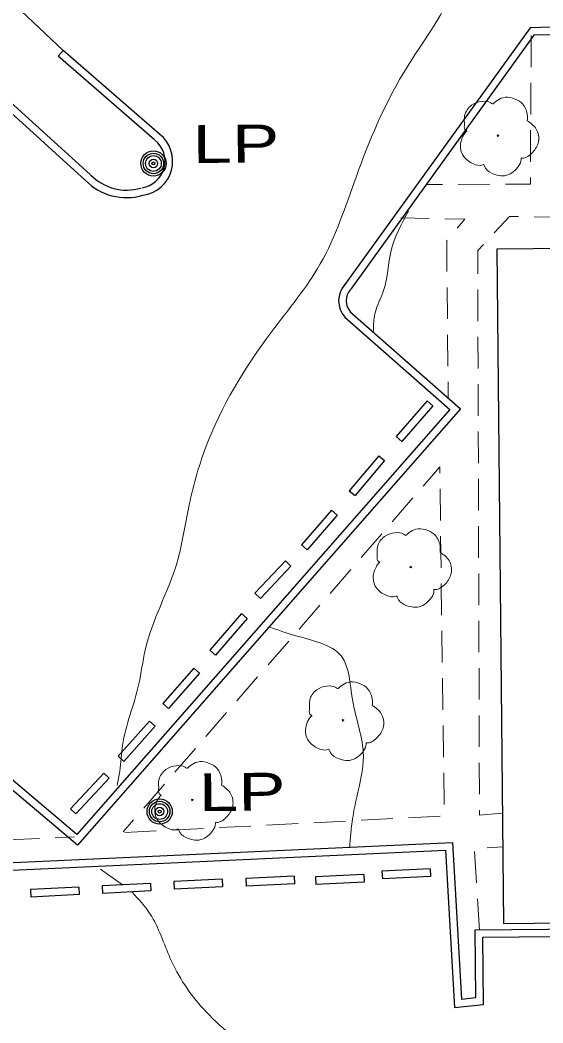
# Model space of a CAD drawing. Extents: x 2361708 to 2370558, y 6977955 to 6991887.
# Drawn here: x 2368967.1 to 2369033.4, y 6989957 to 6990084.2 of the extents above; entities that cross this region are included whole.
import ezdxf

# ---------------------------------------------------------------- set-up
doc = ezdxf.new("R2010")
doc.units = 0
doc.header["$LTSCALE"] = 1.9
for name, color, linetype, lineweight in [('11', 7, 'Continuous', 25), ('13', 7, 'Continuous', 13), ('2', 7, 'Continuous', 25), ('20', 7, 'Continuous', 25), ('29', 7, 'Continuous', 13), ('35', 7, 'Continuous', 13)]:
    doc.layers.add(name, color=color, linetype=linetype, lineweight=lineweight)

msp = doc.modelspace()

# ---------------------------------------------------------------- linework, layer by layer
at = {"layer": '11'}
msp.add_lwpolyline([(2369027.535, 6990055.151), (2369028.399, 6989969.665), (2369096.246, 6989970.351), (2369096.066, 6989988.181), (2369102.336, 6989988.24), (2369102.413, 6989980.191), (2369110.452, 6989980.267), (2369110.378, 6989988.067), (2369111.958, 6989988.082), (2369111.312, 6990055.949)], close=True, dxfattribs=at)
at = {"layer": '13'}
for p, q in [((2369031.896, 6990078.264), (2369031.917, 6990082.264)), ((2369031.853, 6990072.263), (2369031.885, 6990076.264)), ((2369031.82, 6990066.263), (2369031.842, 6990070.263)), ((2369018.657, 6990063.357), (2369020.657, 6990063.366)), ((2369022.657, 6990063.375), (2369026.657, 6990063.393)), ((2369018.957, 6990059.06), (2369015.387, 6990059.146)), ((2369036.286, 6990059.245), (2369032.286, 6990059.287)), ((2369021.289, 6990046.322), (2369021.251, 6990050.321)), ((2369025.144, 6990050.038), (2369025.152, 6990046.038)), ((2369021.346, 6990040.322), (2369021.308, 6990044.322)), ((2369025.161, 6990044.038), (2369025.169, 6990040.038)), ((2369021.384, 6990036.322), (2369021.365, 6990038.322)), ((2369025.178, 6990038.038), (2369025.196, 6990034.038)), ((2369025.205, 6990032.038), (2369025.213, 6990028.038)), ((2369025.222, 6990026.038), (2369025.23, 6990022.038)), ((2369020.354, 6990024.752), (2369020.402, 6990020.752)), ((2369014.283, 6990020.594), (2369016.905, 6990023.619)), ((2369025.239, 6990020.038), (2369025.247, 6990016.038)), ((2369010.347, 6990016.056), (2369012.968, 6990019.081)), ((2369020.432, 6990018.752), (2369020.479, 6990014.752)), ((2369006.41, 6990011.518), (2369009.031, 6990014.543)), ((2369025.256, 6990014.038), (2369025.274, 6990010.038)), ((2369020.509, 6990012.752), (2369020.557, 6990008.753)), ((2369002.473, 6990006.98), (2369005.094, 6990010.006)), ((2369025.284, 6990008.038), (2369025.292, 6990004.038)), ((2369020.586, 6990006.753), (2369020.634, 6990002.753)), ((2368998.536, 6990002.443), (2369001.157, 6990005.468)), ((2369025.301, 6990002.038), (2369025.309, 6989998.038)), ((2368994.599, 6989997.905), (2368997.22, 6990000.93)), ((2369020.663, 6990000.753), (2369020.711, 6989996.753)), ((2368990.662, 6989993.368), (2368993.283, 6989996.393)), ((2369025.318, 6989996.038), (2369025.326, 6989992.037)), ((2369020.74, 6989994.754), (2369020.788, 6989990.754)), ((2368986.725, 6989988.83), (2368989.346, 6989991.855)), ((2369025.335, 6989990.037), (2369025.353, 6989986.037)), ((2369020.817, 6989988.754), (2369020.865, 6989984.754)), ((2368982.788, 6989984.292), (2368985.409, 6989987.317)), ((2368980.167, 6989981.267), (2368981.472, 6989982.779)), ((2369008.355, 6989982.635), (2369004.356, 6989982.427)), ((2369014.351, 6989982.952), (2369010.354, 6989982.744)), ((2369020.349, 6989983.259), (2369016.351, 6989983.051)), ((2368984.365, 6989981.387), (2368980.367, 6989981.179)), ((2368990.362, 6989981.704), (2368986.365, 6989981.496)), ((2368996.36, 6989982.011), (2368992.362, 6989981.803)), ((2369002.357, 6989982.328), (2368998.359, 6989982.12)), ((2368965.555, 6989980.248), (2368969.553, 6989980.436)), ((2368971.553, 6989980.525), (2368974.012, 6989980.638)), ((2369024.722, 6989978.771), (2369024.98, 6989974.783)), ((2369028.337, 6989979.356), (2369026.338, 6989979.236)), ((2369025.109, 6989972.784), (2369025.367, 6989968.796))]:
    msp.add_line(p, q, dxfattribs=at)
for points in [[(2369028.657, 6990063.403), (2369031.807, 6990063.412), (2369031.809, 6990064.262)], [(2369022.539, 6990057.834), (2369023.489, 6990058.953), (2369020.958, 6990059.009)], [(2369030.286, 6990059.308), (2369029.156, 6990059.327), (2369027.205, 6990057.218)], [(2369021.232, 6990052.321), (2369021.205, 6990056.261), (2369021.244, 6990056.311)], [(2369025.85, 6990055.755), (2369025.127, 6990054.978), (2369025.135, 6990052.038)], [(2369018.221, 6990025.131), (2369020.317, 6990027.551), (2369020.325, 6990026.751)], [(2369025.352, 6989984.037), (2369025.358, 6989983.377), (2369028.196, 6989983.624)]]:
    msp.add_lwpolyline(points, dxfattribs=at)
at = {"layer": '2'}
for p, q in [((2368967.234, 6990085.399), (2368972.543, 6990080.379)), ((2368971.909, 6990079.653), (2368972.563, 6990080.36)), ((2368984.151, 6990069.029), (2368971.909, 6990079.653)), ((2368984.784, 6990069.755), (2368972.543, 6990080.379)), ((2369018.718, 6990035.927), (2369014.781, 6990031.399)), ((2369019.444, 6990035.293), (2369015.507, 6990030.766)), ((2369018.718, 6990035.927), (2369019.444, 6990035.293)), ((2369014.781, 6990031.399), (2369015.507, 6990030.766)), ((2369012.594, 6990028.978), (2369008.836, 6990024.532)), ((2369013.33, 6990028.355), (2369009.572, 6990023.909)), ((2369012.594, 6990028.978), (2369013.33, 6990028.355)), ((2369008.836, 6990024.532), (2369009.572, 6990023.909)), ((2369006.599, 6990022.06), (2369002.791, 6990017.664)), ((2369006.599, 6990022.06), (2369007.325, 6990021.427)), ((2369007.325, 6990021.427), (2369003.517, 6990017.031)), ((2369002.791, 6990017.664), (2369003.517, 6990017.031)), ((2369000.74, 6990015.624), (2368996.869, 6990011.547)), ((2369000.74, 6990015.624), (2369001.436, 6990014.961)), ((2369001.436, 6990014.961), (2368997.565, 6990010.884)), ((2368996.869, 6990011.547), (2368997.565, 6990010.884)), ((2368995.164, 6990008.941), (2368991.147, 6990004.323)), ((2368995.89, 6990008.308), (2368991.874, 6990003.69)), ((2368995.164, 6990008.941), (2368995.89, 6990008.308)), ((2368991.147, 6990004.323), (2368991.874, 6990003.69)), ((2368989.139, 6990002.043), (2368985.191, 6989997.565)), ((2368989.139, 6990002.043), (2368989.855, 6990001.41)), ((2368989.855, 6990001.41), (2368985.908, 6989996.933)), ((2368985.191, 6989997.565), (2368985.908, 6989996.933)), ((2368983.503, 6989995.3), (2368979.535, 6989990.852)), ((2368983.503, 6989995.3), (2368984.219, 6989994.656)), ((2368984.219, 6989994.656), (2368980.251, 6989990.208)), ((2368979.535, 6989990.852), (2368980.251, 6989990.208)), ((2368977.705, 6989988.714), (2368973.478, 6989984.203)), ((2368978.401, 6989988.061), (2368974.174, 6989983.55)), ((2368977.705, 6989988.714), (2368978.401, 6989988.061)), ((2368973.478, 6989984.203), (2368974.174, 6989983.55)), ((2369019.103, 6989976.577), (2369012.985, 6989976.269)), ((2369012.985, 6989976.269), (2369013.035, 6989975.31)), ((2369019.103, 6989976.577), (2369019.152, 6989975.618)), ((2368992.704, 6989975.276), (2368986.586, 6989974.968)), ((2368986.586, 6989974.968), (2368986.636, 6989974.008)), ((2368992.704, 6989975.276), (2368992.753, 6989974.316)), ((2369001.841, 6989975.653), (2368995.723, 6989975.345)), ((2368995.723, 6989975.345), (2368995.772, 6989974.385)), ((2369001.841, 6989975.653), (2369001.89, 6989974.693)), ((2369010.669, 6989975.857), (2369004.552, 6989975.549)), ((2369004.552, 6989975.549), (2369004.601, 6989974.589)), ((2369010.669, 6989975.857), (2369010.719, 6989974.898)), ((2369019.152, 6989975.618), (2369013.035, 6989975.31)), ((2368974.543, 6989974.263), (2368968.425, 6989973.955)), ((2368968.425, 6989973.955), (2368968.474, 6989972.995)), ((2368974.543, 6989974.263), (2368974.592, 6989973.304)), ((2368983.618, 6989974.739), (2368977.501, 6989974.431)), ((2368977.501, 6989974.431), (2368977.55, 6989973.472)), ((2368983.668, 6989973.78), (2368977.55, 6989973.472)), ((2368983.618, 6989974.739), (2368983.668, 6989973.78)), ((2368992.753, 6989974.316), (2368986.636, 6989974.008)), ((2369001.89, 6989974.693), (2368995.772, 6989974.385)), ((2369010.719, 6989974.898), (2369004.601, 6989974.589)), ((2368974.592, 6989973.304), (2368968.474, 6989972.995))]:
    msp.add_line(p, q, dxfattribs=at)
for points in [[(2369053.94, 6990080.024), (2369053.808, 6990063.432), (2369035.738, 6990063.35), (2369035.667, 6990083.35), (2369031.768, 6990083.233), (2369008.257, 6990050.678)], [(2369054.9, 6990080.013), (2369054.757, 6990062.481), (2369034.777, 6990062.381), (2369034.706, 6990082.361), (2369032.267, 6990082.288), (2369009.032, 6990050.115)], [(2368925.504, 6989999.047), (2368909.615, 6990014.627), (2368965.895, 6990073.816), (2368975.992, 6990064.631)], [(2368926.178, 6989999.734), (2368910.965, 6990014.65), (2368965.947, 6990072.476), (2368975.349, 6990063.925)], [(2369008.919, 6990047.274), (2369022.968, 6990034.927), (2368974.392, 6989979.602), (2368960.097, 6989991.646)], [(2369008.286, 6990046.558), (2369021.608, 6990034.844), (2368974.289, 6989980.941), (2368960.719, 6989992.382)], [(2368949.187, 6989978.892), (2368949.528, 6989975.665), (2369021.04, 6989978.936), (2369022.181, 6989958.976), (2369025.877, 6989959.381), (2369025.786, 6989967.9), (2369094.913, 6989968.528), (2369095.018, 6989970.139)], [(2368950.147, 6989978.991), (2368950.389, 6989976.663), (2369021.941, 6989979.935), (2369023.08, 6989960.045), (2369024.909, 6989960.242), (2369024.817, 6989968.851), (2369094.014, 6989969.48), (2369094.058, 6989970.12)]]:
    msp.add_lwpolyline(points, dxfattribs=at)
for centre, radius, start, end in [((2368982.069, 6990066.333), 4.369, 277.8722, 51.57746), ((2368982.069, 6990066.333), 3.409, 277.8722, 51.57746), ((2368980.586, 6990068.976), 6.316, 223.96883, 286.62951), ((2368980.586, 6990068.976), 7.276, 223.96883, 286.62951), ((2369010.611, 6990048.634), 3.117, 139.03888, 221.77675), ((2369010.611, 6990048.634), 2.157, 139.03888, 221.77675)]:
    msp.add_arc(centre, radius, start, end, dxfattribs=at)
at = {"layer": '20'}
for centre, radius in [((2368984, 6990066.038), 1.6), ((2368984, 6990066.038), 1.3), ((2368984, 6990066.038), 1), ((2368984, 6990066.038), 0.539), ((2368984, 6990066.038), 0.192), ((2368984.792, 6989983.841), 1.6), ((2368984.792, 6989983.841), 1.3), ((2368984.792, 6989983.841), 1), ((2368984.792, 6989983.841), 0.539), ((2368984.792, 6989983.841), 0.192)]:
    msp.add_circle(centre, radius, dxfattribs=at)
at = {"layer": '29'}
for centre in [(2369027.698, 6990069.574), (2369016.638, 6990014.856), (2369008.043, 6989995.423), (2368988.928, 6989985.321)]:
    msp.add_circle(centre, 0.1, dxfattribs=at)
for points in [[(2369023.732, 6990070.146), (2369023.752, 6990070.156), (2369023.672, 6990070.225), (2369023.435, 6990070.853), (2369023.474, 6990072.134), (2369024.361, 6990073.432), (2369025.666, 6990073.915), (2369026.788, 6990073.725), (2369027.019, 6990073.597), (2369027.089, 6990073.598), (2369027.139, 6990073.638), (2369027.487, 6990073.932), (2369028.352, 6990074.38), (2369029.563, 6990074.312), (2369030.679, 6990073.722), (2369031.412, 6990072.299), (2369031.421, 6990071.439)], [(2369031.41, 6990071.459), (2369032.55, 6990070.4), (2369032.835, 6990068.813), (2369032.128, 6990067.486), (2369031.473, 6990066.94), (2369030.805, 6990066.723), (2369030.656, 6990066.712), (2369030.637, 6990066.602), (2369030.315, 6990065.699), (2369028.776, 6990064.534), (2369026.883, 6990064.816), (2369025.984, 6990065.757), (2369025.913, 6990065.887), (2369025.793, 6990065.866), (2369024.582, 6990065.984), (2369023.313, 6990066.982), (2369022.967, 6990068.619), (2369023.337, 6990069.642), (2369023.663, 6990070.085), (2369023.732, 6990070.136)], [(2369012.673, 6990015.428), (2369012.693, 6990015.438), (2369012.612, 6990015.508), (2369012.376, 6990016.135), (2369012.414, 6990017.415), (2369013.301, 6990018.714), (2369014.607, 6990019.197), (2369015.729, 6990019.007), (2369015.96, 6990018.879), (2369016.03, 6990018.88), (2369016.08, 6990018.921), (2369016.427, 6990019.214), (2369017.293, 6990019.662), (2369018.503, 6990019.594), (2369019.619, 6990019.004), (2369020.352, 6990017.582), (2369020.361, 6990016.721)], [(2369020.351, 6990016.741), (2369021.491, 6990015.682), (2369021.776, 6990014.094), (2369021.068, 6990012.768), (2369020.413, 6990012.222), (2369019.746, 6990012.005), (2369019.596, 6990011.994), (2369019.577, 6990011.883), (2369019.255, 6990010.98), (2369017.716, 6990009.816), (2369015.824, 6990010.098), (2369014.925, 6990011.039), (2369014.853, 6990011.168), (2369014.733, 6990011.147), (2369013.522, 6990011.266), (2369012.253, 6990012.264), (2369011.907, 6990013.9), (2369012.277, 6990014.924), (2369012.603, 6990015.368), (2369012.673, 6990015.418)], [(2369004.077, 6989995.996), (2369004.097, 6989996.005), (2369004.016, 6989996.075), (2369003.78, 6989996.703), (2369003.818, 6989997.983), (2369004.706, 6989999.281), (2369006.011, 6989999.764), (2369007.133, 6989999.575), (2369007.365, 6989999.446), (2369007.435, 6989999.447), (2369007.484, 6989999.488), (2369007.831, 6989999.781), (2369008.697, 6990000.229), (2369009.908, 6990000.161), (2369011.023, 6989999.572), (2369011.757, 6989998.148), (2369011.765, 6989997.289)], [(2369011.755, 6989997.308), (2369012.895, 6989996.249), (2369013.18, 6989994.662), (2369012.473, 6989993.335), (2369011.818, 6989992.789), (2369011.15, 6989992.572), (2369011, 6989992.561), (2369010.981, 6989992.451), (2369010.66, 6989991.548), (2369009.121, 6989990.383), (2369007.228, 6989990.665), (2369006.329, 6989991.606), (2369006.258, 6989991.736), (2369006.138, 6989991.715), (2369004.927, 6989991.833), (2369003.657, 6989992.831), (2369003.312, 6989994.468), (2369003.682, 6989995.492), (2369004.008, 6989995.935), (2369004.077, 6989995.985)], [(2368984.962, 6989985.893), (2368984.982, 6989985.903), (2368984.902, 6989985.972), (2368984.666, 6989986.6), (2368984.703, 6989987.88), (2368985.591, 6989989.179), (2368986.897, 6989989.661), (2368988.019, 6989989.472), (2368988.25, 6989989.344), (2368988.32, 6989989.345), (2368988.369, 6989989.385), (2368988.717, 6989989.679), (2368989.583, 6989990.127), (2368990.793, 6989990.058), (2368991.909, 6989989.469), (2368992.642, 6989988.046), (2368992.65, 6989987.186)], [(2368992.64, 6989987.206), (2368993.781, 6989986.147), (2368994.066, 6989984.559), (2368993.358, 6989983.232), (2368992.703, 6989982.687), (2368992.035, 6989982.47), (2368991.885, 6989982.459), (2368991.866, 6989982.348), (2368991.545, 6989981.445), (2368990.006, 6989980.281), (2368988.113, 6989980.563), (2368987.214, 6989981.504), (2368987.143, 6989981.633), (2368987.023, 6989981.612), (2368985.812, 6989981.731), (2368984.543, 6989982.729), (2368984.197, 6989984.365), (2368984.567, 6989985.389), (2368984.893, 6989985.832), (2368984.962, 6989985.883)]]:
    msp.add_spline(points, degree=3, dxfattribs=at)
at = {"layer": '35'}
msp.add_line((2368977.301, 6989976.519), (2368980.09, 6989974.556), dxfattribs=at)
for points in [[(2369047.828, 6990605.451), (2369038.394, 6990593.231), (2369027.418, 6990575.906), (2369015.841, 6990558.825), (2369000.65, 6990535.639), (2368993.146, 6990516.056), (2368986.096, 6990501.379), (2368978.606, 6990487.716), (2368969.405, 6990472.988), (2368958.108, 6990456.92), (2368955.454, 6990452.025), (2368953.073, 6990437.411), (2368952.752, 6990420.737), (2368959.614, 6990409.992), (2368963.269, 6990401.087), (2368969.023, 6990386.05), (2368979.207, 6990379.327), (2368988.134, 6990377.652), (2368992.144, 6990375.52), (2368991.785, 6990372.277), (2368987.467, 6990362.585), (2368986.816, 6990353.218), (2368988.815, 6990341.807), (2368989.62, 6990331.804), (2368986.922, 6990311.667), (2368979.307, 6990292.194), (2368965.455, 6990270.221), (2368943.017, 6990245.776), (2368913.099, 6990212.86), (2368880.694, 6990176.38), (2368844.682, 6990139.715), (2368811.712, 6990113.21), (2368778.447, 6990087.292), (2368739.578, 6990051.33), (2368711.829, 6990035.275), (2368686.864, 6990022.057), (2368673.109, 6990014.046), (2368669.745, 6990012.454), (2368668.706, 6990013.324), (2368669.63, 6990016.033), (2368674.153, 6990022.016), (2368684.646, 6990033.407), (2368697.173, 6990050.577), (2368697.763, 6990054.743), (2368695.615, 6990054.522), (2368688.933, 6990050.498), (2368671.541, 6990036.962), (2368648.494, 6990028.152), (2368625.507, 6990018.213), (2368603.069, 6990007.409), (2368581.573, 6989999.594), (2368572.511, 6989995.447), (2368567.234, 6989993.027)], [(2368983.929, 6990531.529), (2368979.435, 6990519.356), (2368975.701, 6990506), (2368972.153, 6990495.326), (2368965.023, 6990482.667), (2368952.28, 6990464.985), (2368944.692, 6990449.112), (2368936.279, 6990436.661), (2368930.708, 6990428.388), (2368926.974, 6990420.332), (2368923.178, 6990407.345), (2368925.818, 6990397.9), (2368929.492, 6990388.004), (2368932.253, 6990381.66), (2368935.154, 6990377.288), (2368935.872, 6990367.074), (2368936.658, 6990350.711), (2368934.899, 6990336.894), (2368925.545, 6990315.203), (2368919.061, 6990298.721), (2368917.665, 6990291.017), (2368922.007, 6990291.848), (2368928.932, 6990298.725), (2368940.303, 6990308.073), (2368954.807, 6990321.422), (2368956.934, 6990318.642), (2368952.658, 6990309.771), (2368947.879, 6990300.145), (2368939.818, 6990283.488), (2368927.075, 6990259.465), (2368910.767, 6990240.319), (2368886.835, 6990212.09), (2368866.726, 6990187.627), (2368845.138, 6990163.161), (2368822.496, 6990139.104), (2368799.648, 6990117.845), (2368778.178, 6990104.05), (2368756.592, 6990085.654), (2368734.588, 6990065.974), (2368713.09, 6990048.828), (2368704.692, 6990045.508), (2368705.15, 6990046.662), (2368709.481, 6990052.884), (2368718.059, 6990061.596), (2368727.733, 6990071.708), (2368736.854, 6990082.166), (2368748.659, 6990097.399), (2368759.795, 6990109.476), (2368764.382, 6990117.239), (2368763.943, 6990120.186), (2368757.319, 6990118.552), (2368746.862, 6990109.793), (2368726.432, 6990091.817), (2368699.934, 6990071.484), (2368679.435, 6990058.628), (2368654.88, 6990046.464), (2368626.237, 6990035.071), (2368603.78, 6990024.176), (2368586.487, 6990016.992), (2368573.437, 6990012.767), (2368565.504, 6990008.782), (2368560.239, 6990006.131), (2368556.575, 6990003.426)], [(2368853.219, 6990059.133), (2368853.885, 6990052.128), (2368856.721, 6990043.215), (2368861.67, 6990035.922), (2368871.902, 6990034.729), (2368885.032, 6990039.024), (2368902.946, 6990051.255), (2368919.657, 6990063.835), (2368940.683, 6990082.236), (2368966.691, 6990107.875), (2368986.083, 6990128.76), (2369004.633, 6990148.788), (2369017.829, 6990160.894)], [(2369007.338, 6990118.842), (2369008.712, 6990116.335), (2369015.481, 6990108.079), (2369019.306, 6990102.336), (2369023.615, 6990095.126), (2369021.837, 6990087.469), (2369015.673, 6990077.439), (2369009.697, 6990064.312), (2369005.162, 6990053.288), (2368999.013, 6990044.72), (2368990.613, 6990029.969), (2368988.436, 6990022.268), (2368987.001, 6990015.474), (2368982.947, 6990004.305), (2368982.158, 6990000.027), (2368980.092, 6989992.227), (2368979.743, 6989988.974), (2368979.39, 6989987.16)], [(2369016.349, 6990060.005), (2369014.146, 6990054.984), (2369013.194, 6990049.934), (2369012.092, 6990046.974), (2369011.913, 6990044.783)], [(2368998.7, 6990007.254), (2369001.95, 6990006.175), (2369007.836, 6990003.532), (2369009.248, 6989998.044), (2369010.636, 6989990.877), (2369009.796, 6989985.669), (2369009.262, 6989982.944), (2369008.857, 6989979.26)], [(2368981.299, 6989973.628), (2368983.596, 6989970.839), (2368986.139, 6989965.213), (2368990.29, 6989958.862), (2368997.24, 6989952.578), (2369001.162, 6989949.305), (2369009.48, 6989946.304), (2369018.636, 6989942.571), (2369022.125, 6989939.554), (2369016.55, 6989934.901), (2369012.501, 6989930.482), (2369005.962, 6989925.08), (2369003.341, 6989920.975), (2369000.576, 6989917.298)]]:
    msp.add_spline(points, degree=3, dxfattribs=at)

# ---------------------------------------------------------------- texts
at = {"layer": '20', "width": 1.4}
for p in [(2368984, 6990066.038), (2368984.792, 6989983.841)]:
    msp.add_text('  LP', height=4.8, rotation=0.545, dxfattribs=at).set_placement(p)

doc.saveas('drawing.dxf')
